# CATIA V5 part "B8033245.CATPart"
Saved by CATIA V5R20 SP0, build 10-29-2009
Part number: B8033245
Revision: 5
Definition: design
Nomenclature: B8033245
Source: made
Description: NOT SPECIFIED
Bounding box of the stored display mesh (mm): x -25 to 25, y -25 to 25, z 0 to 45
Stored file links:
  C:\Users\Utente\Desktop\3D files B803\B8033245.CATPart
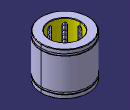
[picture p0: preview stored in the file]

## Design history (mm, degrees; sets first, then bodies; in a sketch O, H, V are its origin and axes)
Body1 "MANIFOLD_SOLID_BREP #38" (main body)
  Solid1: solid without history
Body2 "MANIFOLD_SOLID_BREP #76"
  Solid2: solid without history
Body3 "MANIFOLD_SOLID_BREP #114"
  Solid3: solid without history
Body4 "MANIFOLD_SOLID_BREP #152"
  Solid4: solid without history
Body5 "MANIFOLD_SOLID_BREP #190"
  Solid5: solid without history
Body6 "MANIFOLD_SOLID_BREP #228"
  Solid6: solid without history
Body7 "MANIFOLD_SOLID_BREP #266"
  Solid7: solid without history
Body8 "MANIFOLD_SOLID_BREP #304"
  Solid8: solid without history
Body9 "MANIFOLD_SOLID_BREP #2432"
  Solid9: solid without history
Body10 "MANIFOLD_SOLID_BREP #2470"
  Solid10: solid without history
Body11 "MANIFOLD_SOLID_BREP #2508"
  Solid11: solid without history
Body12 "MANIFOLD_SOLID_BREP #2546"
  Solid12: solid without history
Body13 "MANIFOLD_SOLID_BREP #2584"
  Solid13: solid without history
Body14 "MANIFOLD_SOLID_BREP #2622"
  Solid14: solid without history
Body15 "MANIFOLD_SOLID_BREP #2660"
  Solid15: solid without history
Body16 "MANIFOLD_SOLID_BREP #2698"
  Solid16: solid without history
Body17 "MANIFOLD_SOLID_BREP #2736"
  Solid17: solid without history
Body18 "MANIFOLD_SOLID_BREP #2774"
  Solid18: solid without history
Body19 "MANIFOLD_SOLID_BREP #2812"
  Solid19: solid without history
Body20 "MANIFOLD_SOLID_BREP #2850"
  Solid20: solid without history
Body21 "MANIFOLD_SOLID_BREP #2888"
  Solid21: solid without history
Body22 "MANIFOLD_SOLID_BREP #2926"
  Solid22: solid without history
Body23 "MANIFOLD_SOLID_BREP #2964"
  Solid23: solid without history
Body24 "MANIFOLD_SOLID_BREP #3002"
  Solid24: solid without history
Body25 "MANIFOLD_SOLID_BREP #3040"
  Solid25: solid without history
Body26 "MANIFOLD_SOLID_BREP #3078"
  Solid26: solid without history
Body27 "MANIFOLD_SOLID_BREP #3116"
  Solid27: solid without history
Body28 "MANIFOLD_SOLID_BREP #3154"
  Solid28: solid without history
Body29 "MANIFOLD_SOLID_BREP #3192"
  Solid29: solid without history
Body30 "MANIFOLD_SOLID_BREP #3230"
  Solid30: solid without history
Body31 "MANIFOLD_SOLID_BREP #3268"
  Solid31: solid without history
Body32 "MANIFOLD_SOLID_BREP #3306"
  Solid32: solid without history
Body33 "MANIFOLD_SOLID_BREP #3344"
  Solid33: solid without history
Body34 "MANIFOLD_SOLID_BREP #3382"
  Solid34: solid without history
Body35 "MANIFOLD_SOLID_BREP #3420"
  Solid35: solid without history
Body36 "MANIFOLD_SOLID_BREP #3458"
  Solid36: solid without history
Body37 "MANIFOLD_SOLID_BREP #3496"
  Solid37: solid without history
Body38 "MANIFOLD_SOLID_BREP #3534"
  Solid38: solid without history
Body39 "MANIFOLD_SOLID_BREP #3572"
  Solid39: solid without history
Body40 "MANIFOLD_SOLID_BREP #3610"
  Solid40: solid without history
Body41 "MANIFOLD_SOLID_BREP #3648"
  Solid41: solid without history
Body42 "MANIFOLD_SOLID_BREP #3686"
  Solid42: solid without history
Body43 "MANIFOLD_SOLID_BREP #3724"
  Solid43: solid without history
Body44 "MANIFOLD_SOLID_BREP #3762"
  Solid44: solid without history
Body45 "MANIFOLD_SOLID_BREP #3800"
  Solid45: solid without history
Body46 "MANIFOLD_SOLID_BREP #3838"
  Solid46: solid without history
Body47 "MANIFOLD_SOLID_BREP #3876"
  Solid47: solid without history
Body48 "MANIFOLD_SOLID_BREP #3914"
  Solid48: solid without history
Body49 "MANIFOLD_SOLID_BREP #3952"
  Solid49: solid without history
Body50 "MANIFOLD_SOLID_BREP #3990"
  Solid50: solid without history
Body51 "MANIFOLD_SOLID_BREP #4028"
  Solid51: solid without history
Body52 "MANIFOLD_SOLID_BREP #4066"
  Solid52: solid without history
Body53 "MANIFOLD_SOLID_BREP #4104"
  Solid53: solid without history
Body54 "MANIFOLD_SOLID_BREP #4142"
  Solid54: solid without history
Body55 "MANIFOLD_SOLID_BREP #4180"
  Solid55: solid without history
Body56 "MANIFOLD_SOLID_BREP #4218"
  Solid56: solid without history
Body57 "MANIFOLD_SOLID_BREP #4256"
  Solid57: solid without history
Body58 "MANIFOLD_SOLID_BREP #4294"
  Solid58: solid without history
Body59 "MANIFOLD_SOLID_BREP #4332"
  Solid59: solid without history
Body60 "MANIFOLD_SOLID_BREP #4370"
  Solid60: solid without history
Body61 "MANIFOLD_SOLID_BREP #4408"
  Solid61: solid without history
Body62 "MANIFOLD_SOLID_BREP #4446"
  Solid62: solid without history
Body63 "MANIFOLD_SOLID_BREP #4484"
  Solid63: solid without history
Body64 "MANIFOLD_SOLID_BREP #4522"
  Solid64: solid without history
Body65 "MANIFOLD_SOLID_BREP #4560"
  Solid65: solid without history
Body66 "MANIFOLD_SOLID_BREP #4598"
  Solid66: solid without history
Body67 "MANIFOLD_SOLID_BREP #4636"
  Solid67: solid without history
Body68 "MANIFOLD_SOLID_BREP #4674"
  Solid68: solid without history
Body69 "MANIFOLD_SOLID_BREP #4712"
  Solid69: solid without history
Body70 "MANIFOLD_SOLID_BREP #4750"
  Solid70: solid without history
Body71 "MANIFOLD_SOLID_BREP #4788"
  Solid71: solid without history
Body72 "MANIFOLD_SOLID_BREP #4826"
  Solid72: solid without history
Body73 "MANIFOLD_SOLID_BREP #4864"
  Solid73: solid without history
